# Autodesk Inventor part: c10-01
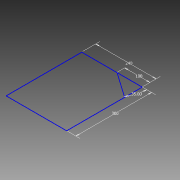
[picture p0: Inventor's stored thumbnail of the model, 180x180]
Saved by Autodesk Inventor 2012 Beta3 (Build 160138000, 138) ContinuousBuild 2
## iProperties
Created: 2011-01
Part Number: c10-01
Material: Default
Document SubType Name: Sheet Metal
Designer: Beta-8540w
Density: 1 g/cm^3
Sheet Metal Rule: Default_mm
Author: Beta-8540w
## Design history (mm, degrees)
sketch "Sketch1"
  geometry: L1 (0, 0)-(240, 0); L2 (240, 0)-(240, 300); L3 (240, 300)-(0, 300); L4 (0, 300)-(0, 0); L5 (140, 300)-(240, 229.979)
  constraints: 10 end point, 2 parallel, 2 point on line, 1 horizontal, 1 perpendicular
  dimensions: "d0" = 240 distance of L3.end L2.end; "d1" = 300 distance of L2.end L1.end; "d2" = 35 deg angle of L3 L5; "d3" = 100 distance from line of L2 L5.start
other parameters: "Thickness" = 0.5 (derived), "BendRadius" = 0.5 (= Thickness), "BendReliefWidth" = 0.5 (= Thickness), "BendReliefDepth" = 0.25 (= 0.5 x Thickness), "CornerReliefSize" = 2 (= 4 x Thickness), "SeamGap" = 0.01, "MinimumRemnant" = 1 (= 2 x Thickness), "TransitionRadius" = 0.5 (= BendRadius), "JacobiRadiusSize" = 0.5 (= BendRadius), "GapSize" = 0.5 (= Thickness)
